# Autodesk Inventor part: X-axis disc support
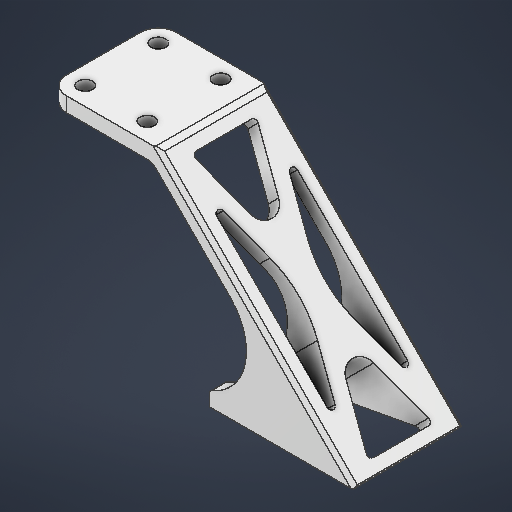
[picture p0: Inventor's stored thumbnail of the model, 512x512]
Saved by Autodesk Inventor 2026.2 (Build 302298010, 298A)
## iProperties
Created: 2026-04
Part Number: X-axis disc support
Material: PBT 플라스틱
Document SubType Name: Modeling
Designer: work
Density: 1.31 g/cm^3
Appearance: 매끄러움 - 흰색
Author: work
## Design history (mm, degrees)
sketch "스케치1"
  geometry: L1 (0, 10)-(0, -10); L2 (-5, 10)-(-5, -10); L3 (5, -10)-(5, 10); L4 (0, 15)-(-25, 15); L5 (-25, 15)-(-25, -15); L6 (-25, -15)-(0, -15); L7 (0, -15)-(0, 15); C1 r 2 at (0, 10); C2 r 2 at (0, -10); A1 r 5 centre (0, 10) between (5, 10) and (-5, 10); A2 r 5 centre (0, -10) between (-5, -10) and (5, -10); 2 further points
  constraints: 16 end point, 5 point on circle, 4 centre point, 4 tangent, 3 parallel, 2 coincident, 1 horizontal, 1 midpoint, 1 perpendicular, 1 vertical
  dimensions: "d0" = 10 distance of point (0, 0) L1.end; "d1" = 10 diameter of A2; "d2" = 4 diameter of C1; "d3" = 4 diameter of C2; "d4" = 25 distance of L6.end L5.end; "d5" = 30 distance of L4.end L5.end
extrude "돌출1" new body sketch "스케치1" distance "d6" = 4; taper "d7" = 0 deg
sketch "스케치2"
  geometry: L1 (25, 0)-(25, 4) reference; L2 (25, 4)-(79, -50); L3 (79, -50)-(39, -50); L4 (39, -50)-(39, -46); L5 (39, -46)-(69.343, -46); L6 (69.343, -46)-(23.343, 0); L7 (0, 0)-(25, 0) reference; L8 (25, 0)-(25, 4) reference; L9 (0, 4)-(25, 4) reference; L10 (0, 0)-(0, 4) reference; L11 (0, 0)-(25, 0) reference; 2 further points
  constraints: 10 end point, 3 perpendicular, 1 parallel, 1 point on line
  dimensions: "d8" = 4 distance between parallel lines of L6 L2; "d9" = 135 deg angle of L7 L6; "d10" = 50 distance between parallel lines of L7 L3; "d11" = 4 distance between parallel lines of L3 L5; "d12" = 40 distance from line of L2.end L4
extrude "돌출2" join sketch "스케치2" stored distance "d13" = 4; taper "d14" = 0 deg
fillet "모깎기1" dims "d15" = 15
fillet "모깎기2" dims "d16" = 4
chamfer "모따기1" distance "d17" = 1; stored, may be unused: second distance "d18" = 2, angle "d19" = 45 deg
sketch "스케치3"
  geometry: L1 (0, 0)-(-74.368, 0) reference; L2 (0, 28)-(0, 0) reference; L3 (-74.368, 28)-(0, 28) reference; L4 (-74.368, 0)-(-74.368, 28) reference; L5 (-3, 3)-(-71.368, 3); L6 (-71.368, 3)-(-71.368, 25); L7 (-71.368, 25)-(-3, 25); L8 (-3, 25)-(-3, 3); L9 (-3, 25)-(-71.368, 3); L10 (-71.368, 25)-(-3, 3); L11 (-64.838, 3)-(-3, 22.899); L12 (-3, 5.101)-(-64.838, 25); L13 (-9.529, 25)-(-71.368, 5.101); L14 (-9.529, 3)-(-71.368, 22.899); A1 r 4 centre (-17.596, 14) between (-18.822, 17.808) and (-18.822, 10.192); A2 r 4 centre (-56.771, 14) between (-55.546, 10.192) and (-55.546, 17.808); A3 r 30 centre (-37.184, -19.616) between (-27.994, 8.942) and (-46.373, 8.942); A4 r 30 centre (-37.184, 47.616) between (-46.373, 19.058) and (-27.994, 19.058); 1 further point
  constraints: 20 end point, 16 point on line, 8 point on circle, 8 tangent, 4 centre point, 4 parallel, 3 other
  dimensions: "d20" = 3 distance between parallel lines of L2 L8; "d22" = 4 distance between parallel lines of L12 L14; "d23" = 2 distance between parallel lines of L14 L10; "d24" = 2 distance between parallel lines of L13 L9; "d25" = 2 distance between parallel lines of L9 L11; "d26" = 4 radius of A1; "d27" = 4 radius of A2; "d28" = 30 radius of A4; "d29" = 30 radius of A3
extrude "돌출3" cut sketch "스케치3" extent not by distance; stored distance "d30" = 0; taper "d31" = 0 deg
fillet "모깎기3" dims "d32" = 1
sketch "스케치4"
  geometry: L1 (21.686, 15)-(21.686, -15) reference; L2 (0, 15)-(21.686, 15) reference; L3 (-5, -10)-(-5, 10) reference; L4 (21.686, -15)-(0, -15) reference; L5 (0, 10)-(17, 10); L6 (17, 10)-(17, -10); L7 (17, -10)-(0, -10); L8 (0, -10)-(0, 10); C1 r 2 at (0, -10) reference; C2 r 2 at (0, 10) reference; C3 r 2 at (17, 10); C4 r 2 at (17, -10); A1 r 5 centre (0, 10) between (0, 15) and (-5, 10) reference; A2 r 5 centre (0, -10) between (-5, -10) and (0, -15) reference; 1 further point
  constraints: 8 end point, 2 centre point, 2 coincident, 2 parallel, 1 horizontal, 1 perpendicular
  dimensions: "d33" = 20 distance of L7.end L5.start; "d34" = 4 diameter of C3; "d35" = 4 diameter of C4; "d36" = 17 distance of L5.start L5.end
extrude "돌출4" cut sketch "스케치4" extent not by distance; stored distance "d37" = 0; taper "d38" = 0 deg
node "솔리드1"
node "투영된 루프1"
node "투영된 루프2"
node "투영된 루프3"
